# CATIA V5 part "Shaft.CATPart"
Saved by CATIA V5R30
Part number: Part2
Material "Iron": density 7870 kg/m3, Young's modulus 2.11e+11 Pa, Poisson ratio 0.291, thermal expansion 1.21e-05 1/K
Bounding box of the stored display mesh (mm): x -20.121 to 20.121, y 0 to 300, z -20.121 to 20.121
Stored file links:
  D:\PROJECTS\CATIA V56R 2020\Resources\Parts File\c19_catia_v5_6r2020_inp\c19_catia_v5_6r2020_inp\c19_catia_v5_6r2020_inp\C19_tut_02.CATPart\Shaft.CATPart
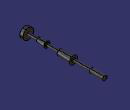
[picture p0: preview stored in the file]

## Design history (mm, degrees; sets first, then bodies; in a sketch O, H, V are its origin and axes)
Body1 (main body), material "Iron"
  Sketch1 on yz-plane, origin (0, 0, 0), H (0, 1, 0), V (0, 0, 1)
    line L1 (0, 0) -> (0, 20.127)
    line L2 (0, 20.127) -> (12.0221, 20.127)
    line L3 (12.0221, 20.127) -> (12.0221, 5.2746)
    point P3 (12.0221, 5.2746)
    line L4 (12.0221, 5.2746) -> (51.1457, 5.2746)
    line L5 (51.1457, 5.2746) -> (51.1457, 8.5349)
    line L6 (51.1457, 8.5349) -> (82.0221, 11.1079)
    line L7 (82.0221, 11.1079) -> (82.0221, 5.2746)
    point P7 (82.0221, 5.2746)
    line L8 (82.0221, 5.2746) -> (132.0221, 5.2746)
    line L9 (132.0221, 5.2746) -> (132.0221, 10.9839)
    line L10 (132.0221, 10.9839) -> (182.0221, 15.1506)
    line L11 (182.0221, 15.1506) -> (182.0221, 5.2746)
    point P11 (182.0221, 5.2746)
    line L12 (182.0221, 5.2746) -> (250, 5.2746)
    line L13 (250, 5.2746) -> (250, 8.5349)
    line L14 (250, 8.5349) -> (300, 8.5349)
    line L15 (300, 8.5349) -> (300, 0)
    point P15 (300, 0)
    axis line L16 (0, 0) -> (300, 0)
    distance L15 L1 = 300
    distance L13 L1 = 250
    distance L11 L7 = 100
    distance L3 L7 = 70
    distance L9 L11 = 50
    vertical: L1 V, L3 V, L5 V, L7 V, L9 V, L11 V, L13 V, L15 V
    horizontal: L2 H, L4 H, L8 H, L12 H, L14 H, L16 H
    coincidence: L6 P3, P7 L4, P11 L4, P15 H
    parallelism: L10 L6
  Shaft1: profile Sketch1, axis Sketch1.L16, angle 360
  Fillet1: radius 2, on edge [face of Shaft1 from Sketch1.L7 | face of Shaft1 from Sketch1.L8]; edge [face of Shaft1 from Sketch1.L4 | face of Shaft1 from Sketch1.L5]; edge [face of Shaft1 from Sketch1.L8 | face of Shaft1 from Sketch1.L9]; edge [face of Shaft1 from Sketch1.L11 | face of Shaft1 from Sketch1.L12]; edge [face of Shaft1 from Sketch1.L12 | face of Shaft1 from Sketch1.L13]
